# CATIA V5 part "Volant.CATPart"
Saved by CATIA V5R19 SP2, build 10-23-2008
Part number: Volant
Publications: "R_volant", "e_volant"
Bounding box of the stored display mesh (mm): x 0 to 50, y -235 to 235, z -235 to 235
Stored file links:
  C:\Users\Romain\Documents\IFMA\2A\cours\S3\Projet CFAO-IAO\IAO\Catia\Volant.CATPart
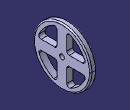
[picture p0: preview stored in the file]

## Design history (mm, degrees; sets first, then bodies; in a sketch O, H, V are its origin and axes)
Parameters
  R_volant = 235 mm
  e_volant = 50 mm
  R_axecentral = 20 mm
  D_entraxe = 40 mm
  R_axedecale = 10 mm
Body1 (main body)
  Sketch1 on yz-plane, origin (0, 0, 0), H (0, 1, 0), V (0, 0, 1)
    circle A1 centre (0, 0) radius 235
    radius A1 = 235 {= R_volant}
  Pad1: profile Sketch1, direction (1, 0, 0), length 50 {= e_volant}
  Sketch2 on end face of Pad1, origin (50, 0, 0), H (0, 1, 0), V (0, 0, 1)
    arc A1 centre (-60, 59.7198) radius 20 from (-59.9064, 39.72) to (-40, 59.7198) ccw
    line L1 (-40, 59.7198) -> (-40, 169.7198)
    arc A2 centre (-60, 169.7198) radius 20 from (-40, 169.7198) to (-68.5534, 187.7984) ccw
    point P6 (-68.5534, 187.7984)
    line L2 (-59.9064, 39.72) -> (-169.9052, 39.205)
    arc A3 centre (-169.9988, 59.2048) radius 20 from (-169.9052, 39.205) to (-188.1173, 67.6735) cw
    arc A4 centre (38.3644, -38.1852) radius 250 from (-188.1173, 67.6735) to (-68.5534, 187.7984) cw
    point P11 (-68.5534, 187.7984)
    length L1 = 110
    distance L1 V = 40
    radius A1 = 20
    radius A2 = 20
    radius A3 = 20
    length L2 = 110
    radius A4 = 250
    distance L2 O = 40
    tangency: L1 A1, A2 L1, L2 A1, A3 L2, A4 A3, A4 A2
    coincidence: P11 A2, A4 P6, P6 P11
  Pocket1: profile Sketch2, direction (-1, 0, 0), through (limit type 3)
  CircPattern1: of Pocket1, instances 4, angular step 90 {= 360.0*1 deg/CircPattern1.AngularNumber}, axis from yz-plane
  Sketch3 on end face of Pad1, origin (50, 0, 0), H (0, 1, 0), V (0, 0, 1)
    circle A1 centre (0, 0) radius 20
    point P1 (0, -40)
    radius A1 = 20 {= R_axecentral}
    distance O P1 = 40 {= D_entraxe}
    coincidence: P1 V
  Pocket2: profile Sketch3, direction (-1, 0, 0), through (limit type 3)
  Fillet1: radius 10, on edge [face of Pad1 from Sketch1.A1 | end face of Pad1]
  Fillet2: radius 10, on edge [start face of Pad1 | face of Pad1 from Sketch1.A1]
